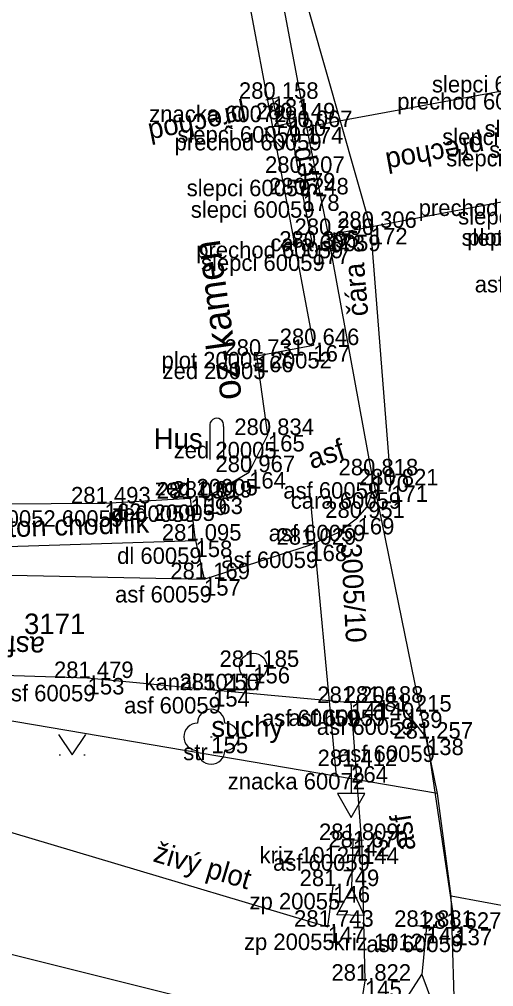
# Model space of a CAD drawing. Extents: x -728659 to -728362, y -1073110 to -1072943.
# Drawn here: x -728525.94 to -728508.67, y -1073039.57 to -1073004.33 of the extents above; entities that cross this region are included whole.
import ezdxf

# ---------------------------------------------------------------- set-up
doc = ezdxf.new("R2010")
doc.units = 0
for name, color, linetype in [('Vrstva 1', 7, 'Continuous'), ('Vrstva 13', 7, 'Continuous'), ('Vrstva 17', 7, 'Continuous'), ('Vrstva 4', 7, 'Continuous'), ('Vrstva 43', 7, 'Continuous'), ('Vrstva 50', 7, 'Continuous'), ('Vrstva 51', 7, 'Continuous'), ('Vrstva 53', 7, 'Continuous'), ('Vrstva 55', 7, 'Continuous'), ('Vrstva 57', 7, 'Continuous'), ('Vrstva 58', 7, 'Continuous'), ('Vrstva 59', 7, 'Continuous'), ('Vrstva 60', 7, 'Continuous'), ('Vrstva 61', 7, 'Continuous'), ('Vrstva 62', 7, 'Continuous'), ('Vrstva 63', 7, 'Continuous')]:
    doc.layers.add(name, color=color, linetype=linetype)

msp = doc.modelspace()

# ---------------------------------------------------------------- linework, layer by layer
at = {"layer": 'Vrstva 1'}
msp.add_lwpolyline([(-728462.112, -1073044.292), (-728486.957, -1073044.611), (-728498.776, -1073043.699), (-728511.695, -1073041.857), (-728514.393, -1073041.361), (-728535.912, -1073035.983), (-728560.369, -1073026.548)], dxfattribs=at)
at = {"layer": 'Vrstva 13'}
msp.add_lwpolyline([(-728519.139, -1073021.757), (-728517.575, -1073020.827), (-728516.889, -1073019.476), (-728517.295, -1073016.589), (-728515.236, -1073016.2)], dxfattribs=at)
at = {"layer": 'Vrstva 17'}
msp.add_line((-728522.835, -1073021.968), (-728542.221, -1073022.127), dxfattribs=at)
for points in [[(-728524.699, -1072966.621), (-728520.715, -1072986.778), (-728519.122, -1072995.457), (-728515.236, -1073016.2)], [(-728531.636, -1073032.342), (-728514.713, -1073037.388), (-728514.509, -1073035.909)]]:
    msp.add_lwpolyline(points, dxfattribs=at)
at = {"layer": 'Vrstva 4'}
for p, q in [((-728513.414, -1073034.243), (-728514.192, -1073034.219)), ((-728510.727, -1073037.434), (-728511.501, -1073037.354))]:
    msp.add_line(p, q, dxfattribs=at)
for points in [[(-728513.803, -1073034.231), (-728513.852, -1073035.969), (-728513.387, -1073036.985), (-728514.386, -1073036.96), (-728513.852, -1073035.969)], [(-728511.114, -1073037.394), (-728511.286, -1073039.124), (-728510.894, -1073040.171), (-728511.888, -1073040.075), (-728511.286, -1073039.124)]]:
    msp.add_lwpolyline(points, dxfattribs=at)
at = {"layer": 'Vrstva 43'}
msp.add_circle((-728517.424, -1073027.925), 0.5, dxfattribs=at)
at = {"layer": 'Vrstva 50'}
msp.add_line((-728518.986, -1073030.471), (-728518.915, -1073030.471), dxfattribs=at)
for centre, start, end in [((-728518.956, -1073029.97), 0, 180), ((-728519.456, -1073030.47), 90, 270), ((-728518.456, -1073030.47), 270, 90), ((-728518.956, -1073030.97), 180, 0)]:
    msp.add_arc(centre, 0.5, start, end, dxfattribs=at)
at = {"layer": 'Vrstva 51'}
for p, q in [((-728516.474, -1073007.179), (-728516.964, -1073007.279)), ((-728515.77, -1073009.926), (-728516.109, -1073007.976)), ((-728515.249, -1073012.65), (-728515.62, -1073010.712)), ((-728519.526, -1073023.322), (-728519.218, -1073024.728)), ((-728513.609, -1073031.539), (-728514.109, -1073031.539))]:
    msp.add_line(p, q, dxfattribs=at)
for points in [[(-728515.484, -1073008.258), (-728518.016, -1072994.823), (-728521.133, -1072978.489), (-728523.451, -1072966.335)], [(-728512.398, -1073021.312), (-728513.144, -1073011.93), (-728518.016, -1072994.823)], [(-728507.377, -1073006.769), (-728515.484, -1073008.258), (-728514.696, -1073012.189), (-728506.595, -1073010.648), (-728507.377, -1073006.769)], [(-728516.719, -1073007.229), (-728516.521, -1073008.209), (-728517.011, -1073008.308), (-728516.348, -1073009.067), (-728516.031, -1073008.11), (-728516.521, -1073008.209)], [(-728535.414, -1073024.787), (-728529.18, -1073024.517), (-728519.218, -1073024.728), (-728515.346, -1073023.472), (-728514.359, -1073023.043), (-728513.624, -1073022.497), (-728513.279, -1073022.092), (-728513.109, -1073021.591), (-728513.091, -1073020.945), (-728514.696, -1073012.189)], [(-728532.088, -1073023.721), (-728519.526, -1073023.322), (-728519.714, -1073021.793), (-728522.835, -1073021.968)], [(-728510.066, -1073037.464), (-728511.097, -1073030.537), (-728511.871, -1073029.55), (-728512.902, -1073029.227), (-728513.865, -1073029.238), (-728518.889, -1073028.771), (-728523.455, -1073028.329), (-728528.834, -1073028.159), (-728535.188, -1073028.207)], [(-728513.553, -1073040.642), (-728513.354, -1073039.355), (-728513.463, -1073034.501), (-728513.865, -1073029.238)], [(-728513.859, -1073031.539), (-728513.859, -1073032.539), (-728514.359, -1073032.539), (-728513.859, -1073033.414), (-728513.359, -1073032.539), (-728513.859, -1073032.539)]]:
    msp.add_lwpolyline(points, dxfattribs=at)
at = {"layer": 'Vrstva 53'}
msp.add_lwpolyline([(-728658.89, -1072943.19), (-728655.13, -1072951.34), (-728641.33, -1072971.93), (-728620.02, -1072997.18), (-728600.31, -1073011.5), (-728598.74, -1073012.6), (-728581.66, -1073022.5), (-728572.55, -1073027.78), (-728541.12, -1073039.22), (-728509.9, -1073046.86), (-728510.22, -1073036.28), (-728510.71, -1073032.54), (-728543.86, -1073026.9), (-728564.68, -1073020.02), (-728582.13, -1073004.22), (-728604.14, -1072988.92), (-728619.81, -1072972.56), (-728640.48, -1072947.72)], dxfattribs=at)
at = {"layer": 'Vrstva 55'}
for p, q in [((-728510.71, -1073032.54), (-728513.08, -1073020.94)), ((-728514.39, -1073031.91), (-728515.38, -1073021.39)), ((-728501.19, -1073037.94), (-728510.22, -1073036.28))]:
    msp.add_line(p, q, dxfattribs=at)
at = {"layer": 'Vrstva 58'}
for p, q in [((-728524.492, -1073031.133), (-728524.442, -1073031.133)), ((-728523.592, -1073031.133), (-728523.542, -1073031.133))]:
    msp.add_line(p, q, dxfattribs=at)
msp.add_lwpolyline([(-728524.517, -1073030.383), (-728524.017, -1073031.133), (-728523.517, -1073030.383)], dxfattribs=at)
at = {"layer": 'Vrstva 59'}
for p, q in [((-728519.005, -1073019.164), (-728519.005, -1073020.364)), ((-728518.505, -1073019.164), (-728518.505, -1073020.364))]:
    msp.add_line(p, q, dxfattribs=at)
msp.add_arc((-728518.755, -1073019.118), 0.254, 349.6111, 190.3889, dxfattribs=at)
at = {"layer": 'Vrstva 60'}
for p, q in [((-728516.719, -1073007.229), (-728516.719, -1073007.229)), ((-728516.109, -1073007.976), (-728516.109, -1073007.976)), ((-728515.484, -1073008.258), (-728515.484, -1073008.258)), ((-728515.77, -1073009.926), (-728515.77, -1073009.926)), ((-728515.62, -1073010.712), (-728515.62, -1073010.712)), ((-728514.696, -1073012.189), (-728514.696, -1073012.189)), ((-728513.144, -1073011.93), (-728513.144, -1073011.93)), ((-728515.249, -1073012.65), (-728515.249, -1073012.65)), ((-728515.236, -1073016.2), (-728515.236, -1073016.2)), ((-728517.295, -1073016.589), (-728517.295, -1073016.589)), ((-728516.889, -1073019.476), (-728516.889, -1073019.476)), ((-728517.575, -1073020.827), (-728517.575, -1073020.827)), ((-728513.091, -1073020.945), (-728513.091, -1073020.945)), ((-728512.398, -1073021.312), (-728512.398, -1073021.312)), ((-728519.139, -1073021.757), (-728519.139, -1073021.757)), ((-728522.835, -1073021.968), (-728522.835, -1073021.968)), ((-728519.714, -1073021.793), (-728519.714, -1073021.793)), ((-728513.624, -1073022.497), (-728513.624, -1073022.497)), ((-728519.526, -1073023.322), (-728519.526, -1073023.322)), ((-728515.346, -1073023.472), (-728515.346, -1073023.472)), ((-728519.218, -1073024.728), (-728519.218, -1073024.728)), ((-728517.424, -1073027.925), (-728517.424, -1073027.925)), ((-728523.455, -1073028.329), (-728523.455, -1073028.329)), ((-728518.889, -1073028.771), (-728518.889, -1073028.771)), ((-728513.865, -1073029.238), (-728513.865, -1073029.238)), ((-728512.902, -1073029.227), (-728512.902, -1073029.227)), ((-728511.871, -1073029.55), (-728511.871, -1073029.55)), ((-728518.95, -1073030.471), (-728518.95, -1073030.471)), ((-728511.097, -1073030.537), (-728511.097, -1073030.537)), ((-728513.859, -1073031.539), (-728513.859, -1073031.539)), ((-728513.803, -1073034.231), (-728513.803, -1073034.231)), ((-728513.463, -1073034.501), (-728513.463, -1073034.501)), ((-728514.509, -1073035.909), (-728514.509, -1073035.909)), ((-728514.713, -1073037.388), (-728514.713, -1073037.388)), ((-728511.114, -1073037.394), (-728511.114, -1073037.394)), ((-728510.066, -1073037.464), (-728510.066, -1073037.464)), ((-728513.354, -1073039.355), (-728513.354, -1073039.355))]:
    msp.add_line(p, q, dxfattribs=at)

# ---------------------------------------------------------------- texts
at = {"layer": 'Vrstva 13'}
msp.add_text('oz-kamen', height=1, rotation=98.005, dxfattribs=at).set_placement((-728517.835, -1073018.137))
at = {"layer": 'Vrstva 51'}
for s, rotation, p in [('přechod', 190.4074, (-728509.088, -1073008.546)), ('slep', 99.8621, (-728515.072, -1073010.744)), ('čára', 94.5462, (-728513.234, -1073015.126)), ('asf', 17.972, (-728515.3, -1073020.727)), ('beton chodnik', 1.8192, (-728527.449, -1073023.234)), ('asf', 178.1898, (-728525.002, -1073026.83)), ('asf', 98.4656, (-728511.507, -1073034.569))]:
    msp.add_text(s, height=0.75, rotation=rotation, dxfattribs=at).set_placement(p)
at = {"layer": 'Vrstva 57'}
msp.add_text('3005/10', height=0.75, rotation=273.0374, dxfattribs=at).set_placement((-728514.236, -1073023.441))
msp.add_text('3171', height=0.75, dxfattribs=at).set_placement((-728525.771, -1073026.731))
at = {"layer": 'Vrstva 60'}
for s, p in [('181', (-728516.719, -1073007.829)), ('180', (-728516.109, -1073008.576)), ('174', (-728515.484, -1073008.858)), ('179', (-728515.77, -1073010.526)), ('178', (-728515.62, -1073011.312)), ('173', (-728514.696, -1073012.789)), ('172', (-728513.144, -1073012.53)), ('177', (-728515.249, -1073013.25)), ('167', (-728515.236, -1073016.8)), ('166', (-728517.295, -1073017.189)), ('165', (-728516.889, -1073020.076)), ('164', (-728517.575, -1073021.427)), ('170', (-728513.091, -1073021.545)), ('171', (-728512.398, -1073021.912)), ('163', (-728519.139, -1073022.357)), ('162', (-728522.835, -1073022.568)), ('159', (-728519.714, -1073022.393)), ('169', (-728513.624, -1073023.097)), ('158', (-728519.526, -1073023.922)), ('168', (-728515.346, -1073024.072)), ('157', (-728519.218, -1073025.328)), ('156', (-728517.424, -1073028.525)), ('153', (-728523.455, -1073028.929)), ('154', (-728518.889, -1073029.371)), ('141', (-728513.865, -1073029.838)), ('140', (-728512.902, -1073029.827)), ('139', (-728511.871, -1073030.15)), ('155', (-728518.95, -1073031.071)), ('138', (-728511.097, -1073031.137)), ('264', (-728513.859, -1073032.139)), ('142', (-728513.803, -1073034.831)), ('144', (-728513.463, -1073035.101)), ('146', (-728514.509, -1073036.509)), ('147', (-728514.713, -1073037.988)), ('143', (-728511.114, -1073037.994)), ('137', (-728510.066, -1073038.064)), ('145', (-728513.354, -1073039.955))]:
    msp.add_text(s, height=0.6, dxfattribs=at).set_placement(p)
at = {"layer": 'Vrstva 61'}
for s, p in [('280.158', (-728517.946, -1073007.229)), ('280.149', (-728517.336, -1073007.976)), ('280.067', (-728516.71, -1073008.258)), ('280.207', (-728516.996, -1073009.926)), ('280.248', (-728516.847, -1073010.712)), ('280.306', (-728514.37, -1073011.93)), ('280.290', (-728515.921, -1073012.189)), ('280.395', (-728516.477, -1073012.65)), ('280.646', (-728516.462, -1073016.2)), ('280.731', (-728518.474, -1073016.589)), ('280.834', (-728518.114, -1073019.476)), ('280.967', (-728518.801, -1073020.827)), ('280.818', (-728514.318, -1073020.945)), ('280.821', (-728513.577, -1073021.312)), ('281.493', (-728524.061, -1073021.968)), ('281.039', (-728520.941, -1073021.793)), ('281.019', (-728520.366, -1073021.757)), ('280.951', (-728514.803, -1073022.497)), ('281.095', (-728520.754, -1073023.322)), ('281.029', (-728516.573, -1073023.472)), ('281.169', (-728520.445, -1073024.728)), ('281.185', (-728518.652, -1073027.925)), ('281.479', (-728524.682, -1073028.329)), ('281.250', (-728520.114, -1073028.771)), ('281.206', (-728515.091, -1073029.238)), ('281.188', (-728514.129, -1073029.227)), ('281.215', (-728513.099, -1073029.55)), ('281.257', (-728512.323, -1073030.537)), ('281.412', (-728515.083, -1073031.539)), ('281.809', (-728515.03, -1073034.231)), ('281.670', (-728514.688, -1073034.501)), ('281.749', (-728515.736, -1073035.909)), ('281.743', (-728515.939, -1073037.388)), ('281.881', (-728512.293, -1073037.394)), ('281.627', (-728511.292, -1073037.464)), ('281.822', (-728514.578, -1073039.355))]:
    msp.add_text(s, height=0.6, dxfattribs=at).set_placement(p)
at = {"layer": 'Vrstva 62'}
for s, p in [('slepci 60059', (-728510.916, -1073006.996)), ('prechod 60059', (-728512.182, -1073007.619)), ('znacka 60072', (-728521.213, -1073008.079)), ('slepci 60059', (-728509.001, -1073008.618)), ('slepci 60059', (-728520.187, -1073008.826)), ('slepci 60059', (-728510.543, -1073008.914)), ('prechod 60059', (-728520.289, -1073009.108)), ('slepci 60059', (-728510.398, -1073009.689)), ('slepci 60059', (-728508.833, -1073009.38)), ('slepci 60059', (-728519.848, -1073010.776)), ('slepci 60059', (-728519.698, -1073011.562)), ('prechod 60059', (-728511.4, -1073011.498)), ('slepci 60059', (-728509.962, -1073011.809)), ('cara 60059', (-728516.803, -1073012.78)), ('slepci 60059', (-728509.838, -1073012.581)), ('plot 20050 20052', (-728509.63, -1073012.573)), ('prechod 60059', (-728519.501, -1073013.039)), ('slepci 60059', (-728519.327, -1073013.5)), ('asf 60059', (-728509.359, -1073014.281)), ('plot 20005 20052', (-728520.763, -1073017.05)), ('zed 20005', (-728520.727, -1073017.439)), ('zed 20005', (-728520.321, -1073020.326)), ('zed 20005', (-728521.007, -1073021.677)), ('asf 60059', (-728516.33, -1073021.795)), ('cara 60059', (-728516.057, -1073022.162)), ('zed 20005', (-728522.571, -1073022.607)), ('dl 60059', (-728522.57, -1073022.643)), ('plot 20052 60059', (-728528.367, -1073022.818)), ('asf 60059', (-728516.863, -1073023.347)), ('dl 60059', (-728522.382, -1073024.172)), ('asf 60059', (-728518.585, -1073024.322)), ('asf 60059', (-728522.457, -1073025.578)), ('kanal 50117', (-728521.387, -1073028.775)), ('asf 60059', (-728526.694, -1073029.179)), ('asf 60059', (-728522.128, -1073029.621)), ('asf 60059', (-728517.104, -1073030.088)), ('asf 60059', (-728516.141, -1073030.077)), ('asf 60059', (-728515.11, -1073030.4)), ('str', (-728519.973, -1073031.321)), ('asf 60059', (-728514.336, -1073031.387)), ('znacka 60072', (-728518.353, -1073032.389)), ('kriz 10127', (-728517.192, -1073035.081)), ('asf 60059', (-728516.702, -1073035.351)), ('zp 20055', (-728517.559, -1073036.759)), ('zp 20055', (-728517.763, -1073038.238)), ('kriz 10127', (-728514.503, -1073038.244)), ('asf 60059', (-728513.305, -1073038.314))]:
    msp.add_text(s, height=0.6, dxfattribs=at).set_placement(p)
at = {"layer": 'Vrstva 63'}
for s, rotation, p in [('přechod', 191.4204, (-728517.747, -1073007.429)), ('živý plot', 343.3968, (-728521.108, -1073035))]:
    msp.add_text(s, height=0.75, rotation=rotation, dxfattribs=at).set_placement(p)
for s, p in [('Hus', (-728521.048, -1073019.983)), ('suchý', (-728518.95, -1073030.471))]:
    msp.add_text(s, height=0.75, dxfattribs=at).set_placement(p)

doc.saveas('drawing.dxf')
